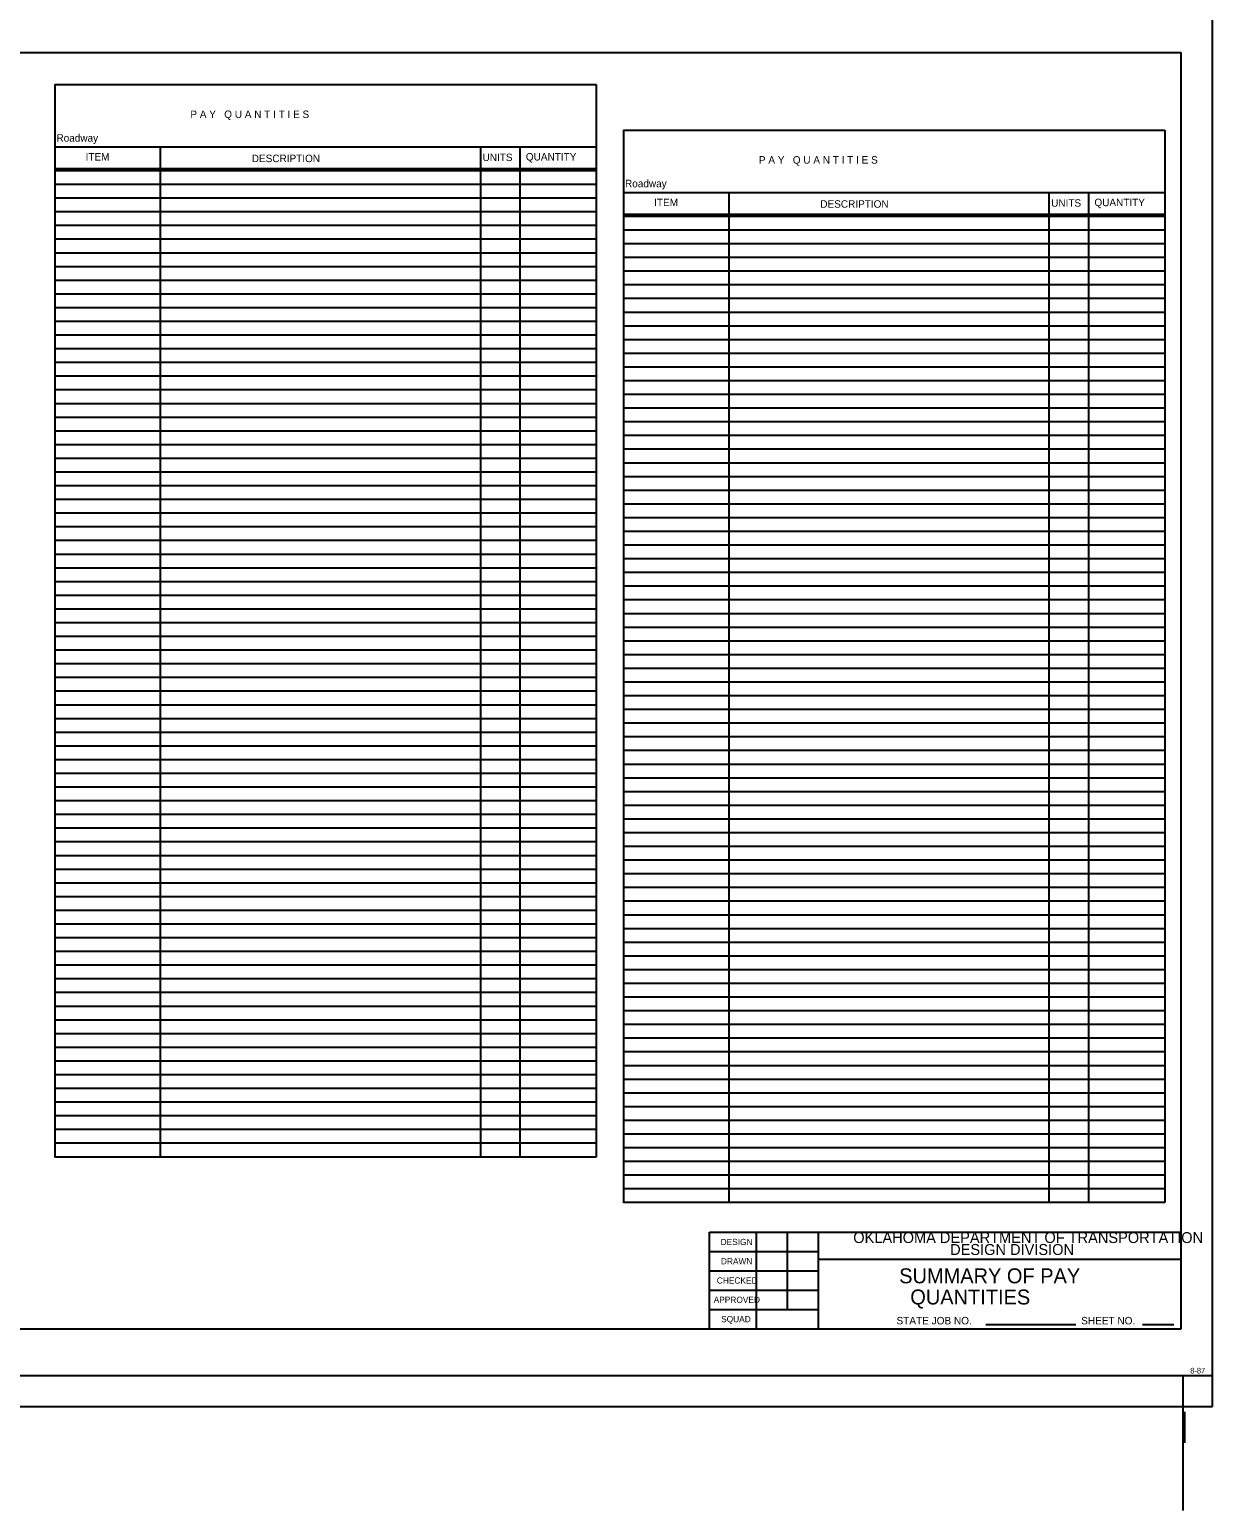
# Model space of a CAD drawing. Extents: x 1789800 to 1793843, y 1789140 to 1792818.
# Drawn here: x 1791500 to 1793399, y 1789140 to 1791518 of the extents above; entities that cross this region are included whole.
import ezdxf

# ---------------------------------------------------------------- set-up
doc = ezdxf.new("R2010")
doc.units = 0
for name, color, linetype in [('Print_Snap_Lines', 7, 'Continuous'), ('Sheet_Border', 7, 'Continuous'), ('Table_Grids', 7, 'Continuous'), ('Title_Block_Text', 7, 'Continuous')]:
    doc.layers.add(name, color=color, linetype=linetype)

msp = doc.modelspace()

# ---------------------------------------------------------------- linework, layer by layer
at = {"layer": 'Print_Snap_Lines'}
for p, q in [((1793352.8, 1789306.5), (1793352.8, 1789356.5)), ((1793352.8, 1789306.5), (1793352.8, 1789356.5)), ((1793355.4, 1789248.5), (1793355.4, 1789298.4))]:
    msp.add_line(p, q, dxfattribs=at)
at = {"layer": 'Sheet_Border'}
for p, q in [((1793399.5, 1789306.5), (1793399.5, 1791606.5)), ((1790100.2, 1791481.5), (1793349.5, 1791481.5)), ((1793349.5, 1789431.5), (1793349.5, 1791481.5)), ((1793349.5, 1790481.2), (1793349.5, 1790481.2)), ((1792592.3, 1789431.6), (1792592.3, 1789586.5)), ((1792592.3, 1789586.5), (1793349.6, 1789586.5)), ((1792667.3, 1789431.6), (1792667.3, 1789586.5)), ((1792717.3, 1789462.6), (1792717.3, 1789586.5)), ((1792767.2, 1789431.6), (1792767.2, 1789586.5)), ((1792592.3, 1789555.5), (1792767.2, 1789555.5)), ((1792767.2, 1789543.5), (1793349.5, 1789543.5)), ((1792592.3, 1789524.5), (1792767.2, 1789524.5)), ((1792592.3, 1789493.6), (1792767.2, 1789493.6)), ((1792592.3, 1789462.6), (1792767.2, 1789462.6)), ((1793036, 1789438.6), (1793180, 1789438.6)), ((1793287.2, 1789438.6), (1793287.2, 1789438.6)), ((1793287.2, 1789438.6), (1793337.4, 1789438.6)), ((1793287.4, 1789438.5), (1793287.4, 1789438.5)), ((1793337.4, 1789438.6), (1793337.4, 1789438.6)), ((1790100.2, 1789431.5), (1793349.5, 1789431.5)), ((1789950.3, 1789356.5), (1793399.5, 1789356.5)), ((1789800.3, 1789306.5), (1793399.5, 1789306.5)), ((1793352.8, 1789139.9), (1793352.8, 1789306.5)), ((1793352.8, 1789139.9), (1793352.8, 1789306.5))]:
    msp.add_line(p, q, dxfattribs=at)
at = {"layer": 'Table_Grids'}
for p, q in [((1791540.9, 1791430.2), (1792410.2, 1791430.2)), ((1791540.9, 1791430.2), (1791540.9, 1789707.4)), ((1792410.2, 1791430.2), (1792410.2, 1789707.4)), ((1792453.7, 1791356.9), (1793323.1, 1791356.9)), ((1792453.7, 1791356.9), (1792453.7, 1789634.2)), ((1793323.1, 1791356.9), (1793323.1, 1789634.2)), ((1791540.9, 1791330.2), (1792410.2, 1791330.2)), ((1791710.2, 1791330.2), (1791710.2, 1789708)), ((1792224.2, 1791330.2), (1792224.2, 1789708)), ((1792287.7, 1791329.9), (1792287.7, 1789707.6)), ((1791540.9, 1791295.2), (1792410.2, 1791295.2)), ((1791540.9, 1791292), (1792410.2, 1791292)), ((1791540.9, 1791270), (1792410.2, 1791270)), ((1791540.9, 1791248), (1792410.2, 1791248)), ((1792453.7, 1791256.9), (1793323.1, 1791256.9)), ((1792623.1, 1791256.9), (1792623.1, 1789634.7)), ((1793137.1, 1791256.9), (1793137.1, 1789634.7)), ((1793200.6, 1791256.6), (1793200.6, 1789634.4)), ((1791540.9, 1791226), (1792410.2, 1791226)), ((1792453.7, 1791221.9), (1793323.1, 1791221.9)), ((1791540.9, 1791204), (1792410.2, 1791204)), ((1792453.7, 1791218.7), (1793323.1, 1791218.7)), ((1791540.9, 1791182), (1792410.2, 1791182)), ((1792453.7, 1791196.7), (1793323.1, 1791196.7)), ((1792453.7, 1791174.7), (1793323.1, 1791174.7)), ((1791540.9, 1791160), (1792410.2, 1791160)), ((1792453.7, 1791152.7), (1793323.1, 1791152.7)), ((1791540.9, 1791138), (1792410.2, 1791138)), ((1792453.7, 1791130.7), (1793323.1, 1791130.7)), ((1791540.9, 1791116), (1792410.2, 1791116)), ((1792453.7, 1791108.7), (1793323.1, 1791108.7)), ((1791540.9, 1791094), (1792410.2, 1791094)), ((1792453.7, 1791086.7), (1793323.1, 1791086.7)), ((1791540.9, 1791072), (1792410.2, 1791072)), ((1792453.7, 1791064.7), (1793323.1, 1791064.7)), ((1791540.9, 1791050), (1792410.2, 1791050)), ((1792453.7, 1791042.7), (1793323.1, 1791042.7)), ((1791540.9, 1791028), (1792410.2, 1791028)), ((1792453.7, 1791020.7), (1793323.1, 1791020.7)), ((1791540.9, 1791006), (1792410.2, 1791006)), ((1791540.9, 1790984), (1792410.2, 1790984)), ((1792453.7, 1790998.7), (1793323.1, 1790998.7)), ((1791540.9, 1790962), (1792410.2, 1790962)), ((1792453.7, 1790976.7), (1793323.1, 1790976.7)), ((1791540.9, 1790940), (1792410.2, 1790940)), ((1792453.7, 1790954.7), (1793323.1, 1790954.7)), ((1791540.9, 1790918), (1792410.2, 1790918)), ((1792453.7, 1790932.7), (1793323.1, 1790932.7)), ((1791540.9, 1790896), (1792410.2, 1790896)), ((1792453.7, 1790910.7), (1793323.1, 1790910.7)), ((1792453.7, 1790888.7), (1793323.1, 1790888.7)), ((1791540.9, 1790874), (1792410.2, 1790874)), ((1792453.7, 1790866.7), (1793323.1, 1790866.7)), ((1791540.9, 1790852), (1792410.2, 1790852)), ((1792453.7, 1790844.7), (1793323.1, 1790844.7)), ((1791540.9, 1790830), (1792410.2, 1790830)), ((1792453.7, 1790822.7), (1793323.1, 1790822.7)), ((1791540.9, 1790808), (1792410.2, 1790808)), ((1792453.7, 1790800.7), (1793323.1, 1790800.7)), ((1791540.9, 1790786), (1792410.2, 1790786)), ((1792453.7, 1790778.7), (1793323.1, 1790778.7)), ((1791540.9, 1790764), (1792410.2, 1790764)), ((1792453.7, 1790756.7), (1793323.1, 1790756.7)), ((1791540.9, 1790742), (1792410.2, 1790742)), ((1792453.7, 1790734.7), (1793323.1, 1790734.7)), ((1791540.9, 1790720), (1792410.2, 1790720)), ((1792453.7, 1790712.7), (1793323.1, 1790712.7)), ((1791540.9, 1790698), (1792410.2, 1790698)), ((1791540.9, 1790676), (1792410.2, 1790676)), ((1792453.7, 1790690.7), (1793323.1, 1790690.7)), ((1791540.9, 1790654), (1792410.2, 1790654)), ((1792453.7, 1790668.7), (1793323.1, 1790668.7)), ((1791540.9, 1790632), (1792410.2, 1790632)), ((1792453.7, 1790646.7), (1793323.1, 1790646.7)), ((1791540.9, 1790610), (1792410.2, 1790610)), ((1792453.7, 1790624.7), (1793323.1, 1790624.7)), ((1791540.9, 1790588), (1792410.2, 1790588)), ((1792453.7, 1790602.7), (1793323.1, 1790602.7)), ((1792453.7, 1790580.7), (1793323.1, 1790580.7)), ((1791540.9, 1790566), (1792410.2, 1790566)), ((1792453.7, 1790558.7), (1793323.1, 1790558.7)), ((1791540.9, 1790544), (1792410.2, 1790544)), ((1792453.7, 1790536.7), (1793323.1, 1790536.7)), ((1791540.9, 1790522), (1792410.2, 1790522)), ((1792453.7, 1790514.7), (1793323.1, 1790514.7)), ((1791540.9, 1790500), (1792410.2, 1790500)), ((1792453.7, 1790492.7), (1793323.1, 1790492.7)), ((1791540.9, 1790478), (1792410.2, 1790478)), ((1792453.7, 1790470.7), (1793323.1, 1790470.7)), ((1791540.9, 1790456), (1792410.2, 1790456)), ((1792453.7, 1790448.7), (1793323.1, 1790448.7)), ((1791540.9, 1790434), (1792410.2, 1790434)), ((1792453.7, 1790426.7), (1793323.1, 1790426.7)), ((1791540.9, 1790412), (1792410.2, 1790412)), ((1791540.9, 1790390), (1792410.2, 1790390)), ((1792453.7, 1790404.7), (1793323.1, 1790404.7)), ((1791540.9, 1790368), (1792410.2, 1790368)), ((1792453.7, 1790382.7), (1793323.1, 1790382.7)), ((1791540.9, 1790346), (1792410.2, 1790346)), ((1792453.7, 1790360.7), (1793323.1, 1790360.7)), ((1791540.9, 1790324), (1792410.2, 1790324)), ((1792453.7, 1790338.7), (1793323.1, 1790338.7)), ((1791540.9, 1790302), (1792410.2, 1790302)), ((1792453.7, 1790316.7), (1793323.1, 1790316.7)), ((1792453.7, 1790294.7), (1793323.1, 1790294.7)), ((1791540.9, 1790280), (1792410.2, 1790280)), ((1792453.7, 1790272.7), (1793323.1, 1790272.7)), ((1791540.9, 1790258), (1792410.2, 1790258)), ((1792453.7, 1790250.7), (1793323.1, 1790250.7)), ((1791540.9, 1790236), (1792410.2, 1790236)), ((1792453.7, 1790228.7), (1793323.1, 1790228.7)), ((1791540.9, 1790214), (1792410.2, 1790214)), ((1792453.7, 1790206.7), (1793323.1, 1790206.7)), ((1791540.9, 1790192), (1792410.2, 1790192)), ((1792453.7, 1790184.7), (1793323.1, 1790184.7)), ((1791540.9, 1790170), (1792410.2, 1790170)), ((1792453.7, 1790162.7), (1793323.1, 1790162.7)), ((1791540.9, 1790148), (1792410.2, 1790148)), ((1792453.7, 1790140.7), (1793323.1, 1790140.7)), ((1791540.9, 1790126), (1792410.2, 1790126)), ((1791540.9, 1790104), (1792410.2, 1790104)), ((1792453.7, 1790118.7), (1793323.1, 1790118.7)), ((1791540.9, 1790082), (1792410.2, 1790082)), ((1792453.7, 1790096.7), (1793323.1, 1790096.7)), ((1791540.9, 1790060), (1792410.2, 1790060)), ((1792453.7, 1790074.7), (1793323.1, 1790074.7)), ((1791540.9, 1790038), (1792410.2, 1790038)), ((1792453.7, 1790052.7), (1793323.1, 1790052.7)), ((1791540.9, 1790016), (1792410.2, 1790016)), ((1792453.7, 1790030.7), (1793323.1, 1790030.7)), ((1792453.7, 1790008.7), (1793323.1, 1790008.7)), ((1791540.9, 1789994), (1792410.2, 1789994)), ((1792453.7, 1789986.7), (1793323.1, 1789986.7)), ((1791540.9, 1789972), (1792410.2, 1789972)), ((1792453.7, 1789964.7), (1793323.1, 1789964.7)), ((1791540.9, 1789950), (1792410.2, 1789950)), ((1792453.7, 1789942.7), (1793323.1, 1789942.7)), ((1791540.9, 1789928), (1792410.2, 1789928)), ((1792453.7, 1789920.7), (1793323.1, 1789920.7)), ((1791540.9, 1789906), (1792410.2, 1789906)), ((1792453.7, 1789898.7), (1793323.1, 1789898.7)), ((1791540.9, 1789884), (1792410.2, 1789884)), ((1792453.7, 1789876.7), (1793323.1, 1789876.7)), ((1791540.9, 1789862), (1792410.2, 1789862)), ((1792453.7, 1789854.7), (1793323.1, 1789854.7)), ((1791540.9, 1789840), (1792410.2, 1789840)), ((1792453.7, 1789832.7), (1793323.1, 1789832.7)), ((1791540.9, 1789818), (1792410.2, 1789818)), ((1791540.9, 1789796), (1792410.2, 1789796)), ((1792453.7, 1789810.7), (1793323.1, 1789810.7)), ((1791540.9, 1789774), (1792410.2, 1789774)), ((1792453.7, 1789788.7), (1793323.1, 1789788.7)), ((1791540.9, 1789752), (1792410.2, 1789752)), ((1792453.7, 1789766.7), (1793323.1, 1789766.7)), ((1791540.9, 1789730), (1792410.2, 1789730)), ((1792453.7, 1789744.7), (1793323.1, 1789744.7)), ((1791540.9, 1789708), (1792410.2, 1789708)), ((1791540.9, 1789707.4), (1791540.9, 1789708)), ((1792453.7, 1789722.7), (1793323.1, 1789722.7)), ((1792453.7, 1789700.7), (1793323.1, 1789700.7)), ((1792453.7, 1789678.7), (1793323.1, 1789678.7)), ((1792453.7, 1789656.7), (1793323.1, 1789656.7)), ((1792453.7, 1789634.7), (1793323.1, 1789634.7)), ((1792453.7, 1789634.2), (1792453.7, 1789634.7))]:
    msp.add_line(p, q, dxfattribs=at)

# ---------------------------------------------------------------- texts
at = {"layer": 'Sheet_Border'}
for s, height, p in [('OKLAHOMA DEPARTMENT OF TRANSPORTATION', 17.5, (1792822.9, 1789569.3)), ('DESIGN', 10, (1792609.9, 1789566)), ('DESIGN DIVISION', 17.5, (1792978.4, 1789550.1)), ('DRAWN', 10, (1792610.4, 1789535)), ('APPROVED', 10, (1792598.8, 1789473.1)), ('STATE JOB NO. ', 12.055, (1792892.3, 1789438.6)), ('SHEET NO. ', 12.05, (1793188.8, 1789438.6)), ('8-87', 9, (1793363.9, 1789359.8))]:
    msp.add_text(s, height=height, dxfattribs=at).set_placement(p)
for s, rotation, p in [('CHECKED', 359.9964, (1792603.8, 1789504.1)), ('SQUAD', 0.0028, (1792610.7, 1789442.1))]:
    msp.add_text(s, height=10, rotation=rotation, dxfattribs=at).set_placement(p)
at = {"layer": 'Table_Grids'}
for s, p in [('P A Y   Q U A N T I T I E S', (1791758.5, 1791376.3)), ('Roadway', (1791543.5, 1791338.3)), ('ITEM', (1791590.3, 1791308)), ('DESCRIPTION', (1791857.1, 1791305.4)), ('UNITS', (1792227.7, 1791307.1)), ('QUANTITY', (1792297.2, 1791308)), ('P A Y   Q U A N T I T I E S', (1792671.4, 1791303)), ('Roadway', (1792456.4, 1791265.1)), ('ITEM', (1792503.2, 1791234.7)), ('UNITS', (1793140.6, 1791233.8)), ('QUANTITY', (1793210.1, 1791234.7)), ('DESCRIPTION', (1792770, 1791232.2))]:
    msp.add_text(s, height=12, dxfattribs=at).set_placement(p)
at = {"layer": 'Title_Block_Text'}
for s, p in [('SUMMARY OF PAY', (1792896.6, 1789504.6)), ('  QUANTITIES', (1792896.6, 1789470.6))]:
    msp.add_text(s, height=24, dxfattribs=at).set_placement(p)

doc.saveas('drawing.dxf')
